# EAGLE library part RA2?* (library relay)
MICROWAVE RELAY FOR ATTENUATOR CIRCUIT NAiS Source: http://www.mew-europe.com/.. en_ds_61308_0000.pdf
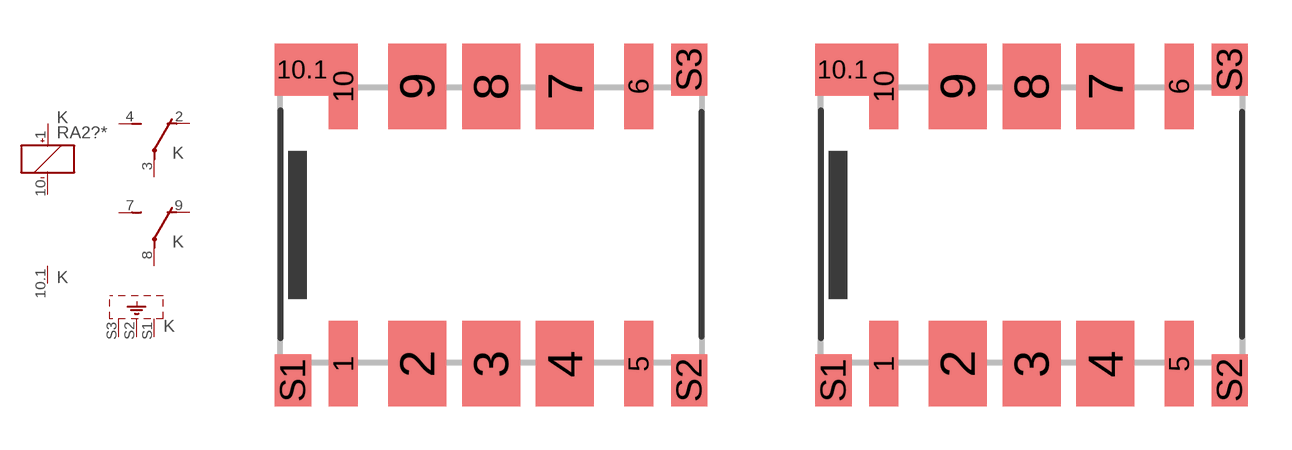
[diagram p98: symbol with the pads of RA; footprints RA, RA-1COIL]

Designator prefix K; gates 1=K+- 2=U 3=U 4=K-PIN S1=SHIELD-3

## RA200A1H (OC_FARNELL: unknown; OC_NEWARK: unknown), RA200A03 (MPN: ARA200A03; OC_FARNELL: unknown; OC_NEWARK: 13P1235), RA200A4V (OC_FARNELL: unknown; OC_NEWARK: unknown), RA200A05 (OC_FARNELL: unknown; OC_NEWARK: unknown), RA200A06 (OC_FARNELL: unknown; OC_NEWARK: unknown), RA200A09 (OC_FARNELL: unknown; OC_NEWARK: unknown), RA200A12 (OC_FARNELL: unknown; OC_NEWARK: unknown), RA200A24 (OC_FARNELL: unknown; OC_NEWARK: unknown), RA200A48 (OC_FARNELL: unknown; OC_NEWARK: unknown)  [RA]
1  1:+  pas
2  2:O  pas
3  2:P  pas
4  2:S  pas
7  3:S  pas
8  3:P  pas
9  3:O  pas
10  1:-  pas
10.1  4:-  pas
S1  S1:SH  pas
S2  S1:SH  pas
S3  S1:SH  pas

## RA210A1H (OC_FARNELL: unknown; OC_NEWARK: unknown), RA210A03 (OC_FARNELL: unknown; OC_NEWARK: unknown), RA210A4H (MF: AROMAT/ MATSUSHITA; MPN: ARA210A4H; OC_FARNELL: unknown; OC_NEWARK: 64K3074), RA210A05 (MF: AROMAT/ MATSUSHITA; MPN: ARA210A05; OC_FARNELL: unknown; OC_NEWARK: 10C4091), RA210A06 (MF: AROMAT/ MATSUSHITA; MPN: ARA210A06; OC_FARNELL: unknown; OC_NEWARK: 10C4092), RA210A09 (OC_FARNELL: unknown; OC_NEWARK: unknown), RA210A12 (MF: AROMAT/ MATSUSHITA; MPN: ARA210A12; OC_FARNELL: unknown; OC_NEWARK: 64K3073), RA210A24 (OC_FARNELL: unknown; OC_NEWARK: unknown)  [RA-1COIL]
1  1:-  pas
2  2:O  pas
3  2:P  pas
4  2:S  pas
7  3:S  pas
8  3:P  pas
9  3:O  pas
10  1:+  pas
10.1  4:-  pas
S1  S1:SH  pas
S2  S1:SH  pas
S3  S1:SH  pas

## Footprint RA (pad centres in mm)
MICROWAVE RELAY FOR ATTENUATOR CIRCUIT NAiS Source: http://www.mew-europe.com/.. en_ds_61308_0000.pdf
smd 1 x 2.94: 1 -5.08,-4.78; 5 5.08,-4.78; 6 5.08,4.78; 10 -5.08,4.78
smd 2 x 2.94: 2 -2.54,-4.78; 3 0,-4.78; 4 2.54,-4.78; 7 2.54,4.78; 8 0,4.78; 9 -2.54,4.78
smd 1.9 x 1.8: 10.1 -6.5,5.35
smd 1.25 x 1.8: S1 -6.82,-5.35; S2 6.82,-5.35; S3 6.82,5.35

## Footprint RA-1COIL (pad centres in mm)
MICROWAVE RELAY FOR ATTENUATOR CIRCUIT NAiS Source: http://www.mew-europe.com/.. en_ds_61308_0000.pdf
smd 1 x 2.94: 1 -5.08,-4.78; 5 5.08,-4.78; 6 5.08,4.78; 10 -5.08,4.78
smd 2 x 2.94: 2 -2.54,-4.78; 3 0,-4.78; 4 2.54,-4.78; 7 2.54,4.78; 8 0,4.78; 9 -2.54,4.78
smd 1.9 x 1.8: 10.1 -6.5,5.35
smd 1.25 x 1.8: S1 -6.82,-5.35; S2 6.82,-5.35; S3 6.82,5.35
